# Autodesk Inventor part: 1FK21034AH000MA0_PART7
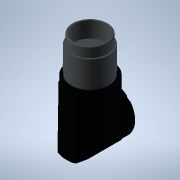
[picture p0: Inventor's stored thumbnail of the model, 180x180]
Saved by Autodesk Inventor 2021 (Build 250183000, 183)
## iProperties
Created: 2025-04
Part Number: 1FK21034AH000MA0_PART7
Material: Generic
Catalog Web Link: www.3dfindit.com
Description: -Servo synchronous motor
Document SubType Name: Modeling
Designer: psAdmin
Mass: 11.1504 g
Surface Area: 35.8996 cm^2
Volume: 11.1504 cm^3
Density: 1 g/cm^3
Appearance: PSOLRGB-176-176-176
Category: PARTsolutions
Title: 1FK21034AH000MA0_PART7
Author: Cadenas PARTsolutions
Comments: Servo synchronous motor
Sending System: PARTsolutions
Preprocessor: ST-DEVELOPER v19.3
PSOL_IDENT_0: {$CADENAS_DATA/23d-libs/siemens_ag/_cat_/ec/b7/1fk21034ah000ma0.prj},213 {VTYP=3D},{NB=1FK21034AH000
PSOL_IDENT_1: MA0_PART7},{LINA=1FK21034AH000MA0_PART7},{NN=1FK21034AH000MA0_PART7},{NOPRJ=TRUE},{DATE=19.08.2025 1
PSOL_IDENT_2: 4:01:05},{GEOMDATE=30.07.2025 02:01:02},{VERSION=},{LINEID=10},{WBVAR=},{WBNUMERIC=}  {NB=1FK21034AH
PSOL_IDENT_3: 000MA0_PART7},{LINA=1FK21034AH000MA0_PART7},{KT=DUMMY},{PREVIEW=../../../_pool_/7c/50/p_d211_xx_0093
PSOL_IDENT_4: 2j.png},{DESCSHORT=SIMOTICS S-1FK2 HD, SINAMICS S210 3AC 400V-480V, 1.01 Nm, 4500 rpm},{DESCLONG=SIM
PSOL_IDENT_5: OTICS S-1FK2 HD servo motor M0=1.27 Nm; PN = 0.48 kW at nN=4500 rpm (380-480 V); PN = 0.3 kW at nN=2
PSOL_IDENT_6: 500 rpm (200-240 V); degree of protection IP64; cylindrical shaft D14 x 30 mm; absolute encoder 22-b
PSOL_IDENT_7: it + 12-bit multiturn (encoder AM22DQC); with OCC interface; plug size M17, rotatable; SIMOTICS S-1F
PSOL_IDENT_8: K2 servomotorfor a wide range of uses in industrial environments. SIMOTICS S‑1FK2 servomotors are co
PSOL_IDENT_9: mpact synchronous motors with a high dynamic performance that set themselves apart as a result of th
PSOL_IDENT_10: eir high power density, degree of protection and overload capability. The motors are available in tw
PSOL_IDENT_11: o variants: as High Dynamic variant (highest dynamic performance as a result of the low intrinsic mo
PSOL_IDENT_12: ment of inertia for applications demanding a high dynamic performance with low moved masses) - and a
PSOL_IDENT_13: s Compact variant (precise and stable closed-loop control for medium up to large moved masses as a r
PSOL_IDENT_14: esult of a medium intrinsic moment of inertia). SIMOTICSS‑1FK2 servomotors fully exploit their stren
PSOL_IDENT_15: gths in a system with the SINAMICSS210 frequency converter and simple connection using the one cable
PSOL_IDENT_16: connection (OCC). Advantages include the short control and positioning times, fast and precise corr
PSOL_IDENT_17: ection of disturbing quantities as well as stable control with a high dynamic performance. The servo
PSOL_IDENT_18: motors can be configured to address a wide range of requirements. For example with and without hold
PSOL_IDENT_19: ing brake, IP64 or IP65 degree of protection, singleturn or multiturn absolute encoders - to name ju
PSOL_IDENT_20: st a few. Further, the servomotors are available in different shaft heights extending from 20 to 100
PSOL_IDENT_21: . A shaft sealing ring is available to achieve an IP65 degree of protection and for subsequent mount
PSOL_IDENT_22: ing at the motor or as spare part. SIMOTICS - the optimum motor for each and every motion control ap
PSOL_IDENT_23: plication.},{INTNO=4034106444822},{SUPPLIERALTNO=1FK2103-4AH00-0MA0},{MANUID=1FK21034AH000MA0},{MANU
PSOL_IDENT_24: NAME=Siemens},{MANUTYPEDESC=SYNCHRONOUS MOTOR 1FK2 HD 1,27 NM},{AAU732=SIMOTICS},{AAO057=S-1FK2},{AA
PSOL_IDENT_25: U734=SIMOTICS S-1FK2 HD servo motor M0=1.27 Nm; PN = 0.48 kW at nN=4500 rpm (380-480 V); PN = 0.3 kW
PSOL_IDENT_26: at nN=2500 rpm (200-240 V); degree of protection IP64; cylindrical shaft D14 x 30 mm; absolute enco
PSOL_IDENT_27: der 22-bit + 12-bit multiturn (encoder AM22DQC); with OCC interface; plug size M17, rotatable;},{AAW
PSOL_IDENT_28: 338=SYNCHRONOUS MOTOR 1FK2 HD 1,27 NM},{AAO742=SIMOTICS},{AAO663=4034106444822},{NOCUPEROU=1},{PRICE
PSOL_IDENT_29: QUANTITY=1},{QUANTITYMIN=1},{QUANTITYINT=1},{CTN=85015100},{COO=RO},{AAO676=1FK2103-4AH00-0MA0},{AAO
PSOL_IDENT_30: 677=Siemens AG},{ORDERUNIT=C62},{CONTENTUNIT=C62}
NB: 1FK21034AH000MA0_PART7
NT: Servo synchronous motor
NBSYN: $MANUID._PART7
LINA: 1FK21034AH000MA0_PART7
CATALOG: SIEMENS
PREVIEW: ../../../_pool_/7c/50/p_d211_xx_00932j.png
DESCSHORT: SIMOTICS S-1FK2 HD, SINAMICS S210 3AC 400V-480V, 1.01 Nm, 4500 rpm
DESCLONG: SIMOTICS S-1FK2 HD servo motor M0=1.27 Nm; PN = 0.48 kW at nN=4500 rpm (380-480 V); PN = 0.3 kW at nN=2500 rpm (200-240 V); degree of protection IP64; cylindric
INTNO: 4034106444822
SUPPLIERALTNO: 1FK2103-4AH00-0MA0
MANUID: 1FK21034AH000MA0
MANUNAME: Siemens
MANUTYPEDESC: SYNCHRONOUS MOTOR 1FK2 HD 1,27 NM
AAU732: SIMOTICS
AAO057: S-1FK2
AAU734: SIMOTICS S-1FK2 HD servo motor M0=1.27 Nm; PN = 0.48 kW at nN=4500 rpm (380-480 V); PN = 0.3 kW at nN=2500 rpm (200-240 V); degree of protection IP64; cylindric
AAW338: SYNCHRONOUS MOTOR 1FK2 HD 1,27 NM
AAO742: SIMOTICS
AAO663: 4034106444822.0
NOCUPEROU: 1
PRICEQUANTITY: 1
QUANTITYMIN: 1
QUANTITYINT: 1
CTN: 85015100
COO: RO
ARTICLENO: 1FK21034AH000MA0_PART7
BOMINFO: 1FK21034AH000MA0_PART7
CREATOR: CADENAS GmbH
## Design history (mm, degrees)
feature "2025_04_17_15_01_37_0283"
body "Solid1"
